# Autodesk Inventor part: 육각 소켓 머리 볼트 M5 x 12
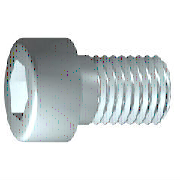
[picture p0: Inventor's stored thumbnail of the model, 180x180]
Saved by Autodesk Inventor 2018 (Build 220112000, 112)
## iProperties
Created: 2012-02
Part Number: 육각 소켓 머리 볼트 M5 x 12
Material: 강철, 연강
Description: 6각 소켓 머리 캡 나사
Document SubType Name: Modeling
Standard: ISO 4762
Designer: mdu-01
Standard Revision: Fourth edition 2004-03-01
Standards Organization: ISO
Language: ko-KR
Size Designation: M5 x 12
Categories: <MemberInstance><Categories><Category DisplayName="조임쇠" InternalName="e4da775c-781d-43d5-af7c-5136215cf5a6" Mnemonic="FSTN"><Category DisplayName="볼트" InternalN
Density: 7.75 g/cm^3
Appearance: 강철
Author: mdu-01
IsCustomPart: 1
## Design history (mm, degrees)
sketch "스케치1"
  geometry: L1 (-1.167, 0)-(12, 0); L2 (12, 0)-(12, 2.5); L3 (12, 2.5)-(2, 2.5); L4 (2, 2.5)-(1.509, 2.5); L5 (1.509, 2.5)-(0, 2.5); L6 (0, 2.5)-(0, 4.25); L7 (0, 4.25)-(-5, 4.25); L8 (-5, 4.25)-(-5, 2.309); L9 (-5, 2.309)-(-2.5, 2.309); L10 (-2.5, 2.309)-(-1.167, 0); L11 (-8.4, 0)-(15.4, 0) reference; L12 (0, -0.85)-(0, 5.1) reference; L13 (2, 2.5)-(0, 2.5)
  constraints: 22 end point, 6 parallel, 2 collinear, 2 perpendicular, 1 horizontal, 1 point on line
  dimensions: "d1" = 10 distance from line of L3.end L2 (= GEL); "d2" = 0.49086 distance of L4.end L3.end (computed from GAL); "d3" = 5 distance between parallel lines of L8 L6 (= KOH); "d4" = 2.5 distance of L8.end L9.end (= INTI); "d5" = 60 deg angle of L10 L1; "d6" = 5 diameter of L3 L1 (= GD); "d7" = 5 diameter of L5 L1 (= BDM); "d8" = 4.6188 diameter of L9 L1 (= 1.1547 x SW); "d9" = 8.5 diameter of L7 L1 (= KOD); "d26" = 12 distance between parallel lines of L12 L2 (= NLG)
revolve "본체" sketch "스케치1" stored, may be unused: angle "d10" = 90 deg
sketch "스케치2"
  geometry: L1 (0, -5.95)-(0, 5.95) reference; L2 (-5.95, 0)-(5.95, 0) reference; L3 (2.309, 0)-(1.155, -2); L4 (1.155, -2)-(-1.155, -2); L5 (-1.155, -2)-(-2.309, 0); L6 (-2.309, 0)-(-1.155, 2); L7 (-1.155, 2)-(1.155, 2); L8 (1.155, 2)-(2.309, 0); 2 further points
  constraints: 12 end point, 1 coincident, 1 horizontal alignment, 1 point on line, 12 other
extrude "슬롯" join sketch "스케치2" stored distance "d11" = 10; taper "d12" = 0 deg
workplane "Work Plane1"
fillet "Fillet2" dims "d30" = 0.1 (= R)
body "Solid1"
fillet "모깎기1" dims "d17" = 0.5 (= RR)
feature "스레드" dims "d13" = 10 (= GEL), "d14" = 0
chamfer "모따기1" distance "d15" = 0.49076 (= -0.5 x SPD + 0.5 x GD); stored, may be unused: second distance "d16" = 0.49076 (= GUL), angle "d27" = 45 deg
other parameters: "GD" = 5 [user parameter; used in 2 equation terms], "NLG" = 12 [user parameter; used in 1 equation term], "GEL" = 10 [user parameter; used in 2 equation terms], "KOD" = 8.5 [user parameter; used in 1 equation term], "KOH" = 5 [user parameter; used in 1 equation term], "INTI" = 2.5 [user parameter; used in 1 equation term], "GAL" = 0.49076 (= 0.61345 x PTC) [user parameter; used in 1 equation term], "GUL" = 0.49076 (= 0.61345 x PTC) [user parameter; used in 1 equation term], "BDM" = 5 (= NND) [user parameter; used in 1 equation term], "SW" = 4 [user parameter; used in 2 equation terms], "RR" = 0.5 [user parameter; used in 1 equation term], "SPD" = 4.01848 (= NND - 1.2269 x PTC) [user parameter; used in 1 equation term], "d19" = 0, "d28" = 0, "d29" = 0, "R" = 0.1 [user parameter; used in 1 equation term], "TOA" = 30 deg [user parameter], "GD1" = 4.01848 (= THREADDIA - 1.2269 x PTC) [user parameter], "THREADDIA" = 5 [user parameter; used in 1 equation term], "FAWI" = 45 deg [user parameter], "TPU" = 12.5 (computed from PTC) [user parameter], "PTC" = 0.8 [user parameter; used in 5 equation terms], "NND" = 5 [user parameter; used in 2 equation terms], "E0" = 4.62 (= 1.155 x SW) [user parameter]
